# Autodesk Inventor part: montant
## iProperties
Created: 2011-01
Part Number: montant
Document SubType Name: Modeling
Designer: eric
Density: 1 g/cm^3
Mass: 31.1053 g
Surface Area: 330.938 cm^2
Volume: 31.1053 cm^3
Author: eric
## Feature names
1. Base1
